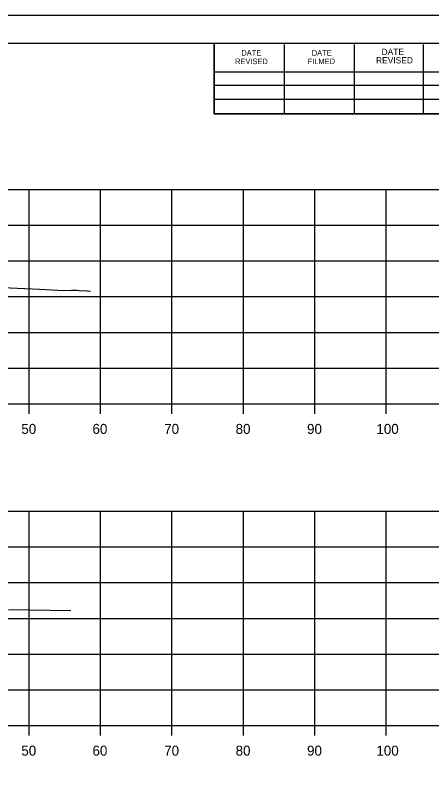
# Model space of a CAD drawing. Extents: x 1103485 to 1107180, y 2010593 to 2011873.
# Drawn here: x 1107065.3 to 1107123.6, y 2010699.1 to 2010806.2 of the extents above; entities that cross this region are included whole.
import ezdxf

# ---------------------------------------------------------------- set-up
doc = ezdxf.new("R2010")
doc.units = 0
for name, color, linetype in [('R_Axis', 7, 'Continuous'), ('R_Axis Annot', 7, 'Continuous'), ('R_Border', 7, 'Continuous'), ('R_Exist Surface', 7, 'Continuous'), ('R_Grid', 7, 'Continuous'), ('R_No Plot', 7, 'Continuous')]:
    doc.layers.add(name, color=color, linetype=linetype)

msp = doc.modelspace()

# ---------------------------------------------------------------- linework, layer by layer
at = {"layer": 'R_Axis'}
for p, q in [((1106867.18, 2010751.82), (1107167.18, 2010751.82)), ((1107067.18, 2010750.42), (1107067.18, 2010751.82)), ((1107077.18, 2010750.42), (1107077.18, 2010751.82)), ((1107087.18, 2010750.42), (1107087.18, 2010751.82)), ((1107097.18, 2010750.42), (1107097.18, 2010751.82)), ((1107107.18, 2010750.42), (1107107.18, 2010751.82)), ((1107117.18, 2010750.42), (1107117.18, 2010751.82)), ((1106867.18, 2010706.82), (1107167.18, 2010706.82)), ((1107067.18, 2010705.42), (1107067.18, 2010706.82)), ((1107077.18, 2010705.42), (1107077.18, 2010706.82)), ((1107087.18, 2010705.42), (1107087.18, 2010706.82)), ((1107097.18, 2010705.42), (1107097.18, 2010706.82)), ((1107107.18, 2010705.42), (1107107.18, 2010706.82)), ((1107117.18, 2010705.42), (1107117.18, 2010706.82))]:
    msp.add_line(p, q, dxfattribs=at)
at = {"layer": 'R_Border'}
for p, q in [((1106859.18, 2010802.28), (1107175.36, 2010802.28)), ((1107093.1, 2010792.4), (1107093.1, 2010802.28)), ((1107102.96, 2010792.4), (1107102.96, 2010802.08)), ((1107112.72, 2010792.4), (1107112.72, 2010802.08)), ((1107122.4, 2010792.4), (1107122.4, 2010802.08)), ((1107093.1, 2010798.26), (1107132.26, 2010798.26)), ((1107093.1, 2010796.4), (1107132.26, 2010796.4)), ((1107093.1, 2010792.4), (1107093.1, 2010794.46)), ((1107093.1, 2010794.46), (1107132.26, 2010794.46)), ((1107175.36, 2010792.4), (1107093.1, 2010792.4))]:
    msp.add_line(p, q, dxfattribs=at)
at = {"layer": 'R_Exist Surface'}
for points in [[(1107056.34, 2010768.43), (1107068.63, 2010767.86), (1107072.03, 2010767.7), (1107073.12, 2010767.71), (1107073.89, 2010767.71), (1107074.25, 2010767.7), (1107075.3, 2010767.62), (1107075.78, 2010767.59)], [(1107064.31, 2010723.05), (1107073.05, 2010722.93)]]:
    msp.add_lwpolyline(points, dxfattribs=at)
at = {"layer": 'R_Grid'}
for p, q in [((1106867.18, 2010781.82), (1107167.18, 2010781.82)), ((1107067.18, 2010751.82), (1107067.18, 2010781.82)), ((1107077.18, 2010751.82), (1107077.18, 2010781.82)), ((1107087.18, 2010751.82), (1107087.18, 2010781.82)), ((1107097.18, 2010751.82), (1107097.18, 2010781.82)), ((1107107.18, 2010751.82), (1107107.18, 2010781.82)), ((1107117.18, 2010751.82), (1107117.18, 2010781.82)), ((1106867.18, 2010776.82), (1107167.18, 2010776.82)), ((1106867.18, 2010771.82), (1107167.18, 2010771.82)), ((1106867.18, 2010766.82), (1107167.18, 2010766.82)), ((1106867.18, 2010761.82), (1107167.18, 2010761.82)), ((1106867.18, 2010756.82), (1107167.18, 2010756.82)), ((1106867.18, 2010751.82), (1107167.18, 2010751.82)), ((1106867.18, 2010736.82), (1107167.18, 2010736.82)), ((1107067.18, 2010706.82), (1107067.18, 2010736.82)), ((1107077.18, 2010706.82), (1107077.18, 2010736.82)), ((1107087.18, 2010706.82), (1107087.18, 2010736.82)), ((1107097.18, 2010706.82), (1107097.18, 2010736.82)), ((1107107.18, 2010706.82), (1107107.18, 2010736.82)), ((1107117.18, 2010706.82), (1107117.18, 2010736.82)), ((1106867.18, 2010731.82), (1107167.18, 2010731.82)), ((1106867.18, 2010726.82), (1107167.18, 2010726.82)), ((1106867.18, 2010721.82), (1107167.18, 2010721.82)), ((1106867.18, 2010716.82), (1107167.18, 2010716.82)), ((1106867.18, 2010711.82), (1107167.18, 2010711.82)), ((1106867.18, 2010706.82), (1107167.18, 2010706.82))]:
    msp.add_line(p, q, dxfattribs=at)
at = {"layer": 'R_No Plot'}
msp.add_line((1106846.78, 2010806.17), (1107180.12, 2010806.17), dxfattribs=at)
for points in [[(1106846.78, 2010806.17), (1107180.12, 2010806.17), (1107180.12, 2010592.83), (1106846.78, 2010592.83)], [(1107093.1, 2010802.28), (1107093.1, 2010792.4), (1107128.84, 2010792.4), (1107128.84, 2010789.48), (1107152.04, 2010789.48), (1107152.04, 2010765.14), (1107175.36, 2010765.14), (1107175.36, 2010596.82), (1106859.18, 2010596.82), (1106859.18, 2010802.28)]]:
    msp.add_lwpolyline(points, close=True, dxfattribs=at)

# ---------------------------------------------------------------- texts
at = {"layer": 'R_Axis Annot'}
for s, p in [('50', (1107066.1, 2010747.62)), ('60', (1107076.06, 2010747.62)), ('70', (1107086.1, 2010747.62)), ('80', (1107096.1, 2010747.62)), ('90', (1107106.1, 2010747.62)), ('100', (1107115.81, 2010747.62)), ('50', (1107066.1, 2010702.62)), ('60', (1107076.06, 2010702.62)), ('70', (1107086.1, 2010702.62)), ('80', (1107096.1, 2010702.62)), ('90', (1107106.1, 2010702.62)), ('100', (1107115.81, 2010702.62))]:
    msp.add_text(s, height=1.4, dxfattribs=at).set_placement(p)
at = {"layer": 'R_Border'}
for s, height, p in [('DATE', 0.782, (1107096.9, 2010800.52)), ('DATE', 0.782, (1107106.76, 2010800.52)), ('DATE', 0.879, (1107116.54, 2010800.62)), ('REVISED', 0.782, (1107096.02, 2010799.34)), ('FILMED', 0.782, (1107106.18, 2010799.34)), ('REVISED', 0.879, (1107115.76, 2010799.44))]:
    msp.add_text(s, height=height, rotation=360, dxfattribs=at).set_placement(p)

doc.saveas('drawing.dxf')
